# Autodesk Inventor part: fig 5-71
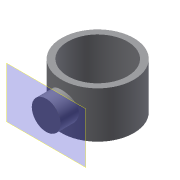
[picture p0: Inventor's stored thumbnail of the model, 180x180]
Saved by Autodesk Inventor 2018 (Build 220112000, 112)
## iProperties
Shininess: 64.0
Length Units: 11269
Angle Units: 11279
Time Units: 11290
Mass Units: 11283
Length Display Precision: 3
Angle Display Precision: 2
Compacted: True
Part Number: fig 5-71
Document SubType Name: Modeling
Created: 2002-12
Designer: deepak
Density: 1 g/cm^3
Material: Generic
Appearance: Default
Density: 0.0
Volumn: 0.0
Area: 0.0
PropertySet Name: Model Information
Control State: 0
Master: False
Checked Out: False
Author: deepak
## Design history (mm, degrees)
sketch "Sketch1"
  geometry: C1 r 23.454 at (0, 0); C2 r 19.43 at (0, 0)
  constraints: 2 centre point, 1 coincident, 1 concentric
extrude "Extrusion1" new body sketch "Sketch1" stored distance "d0" = 30; taper "d1" = 0 deg
workplane "Work Plane1"
workplane "Work Plane2"
sketch "Sketch2"
  geometry: C1 r 9.343 at (0, 0)
  constraints: 1 centre point
extrude "Extrusion2" join sketch "Sketch2" stored distance "d4" = 10; taper "d5" = 0 deg
body "Solid1"
